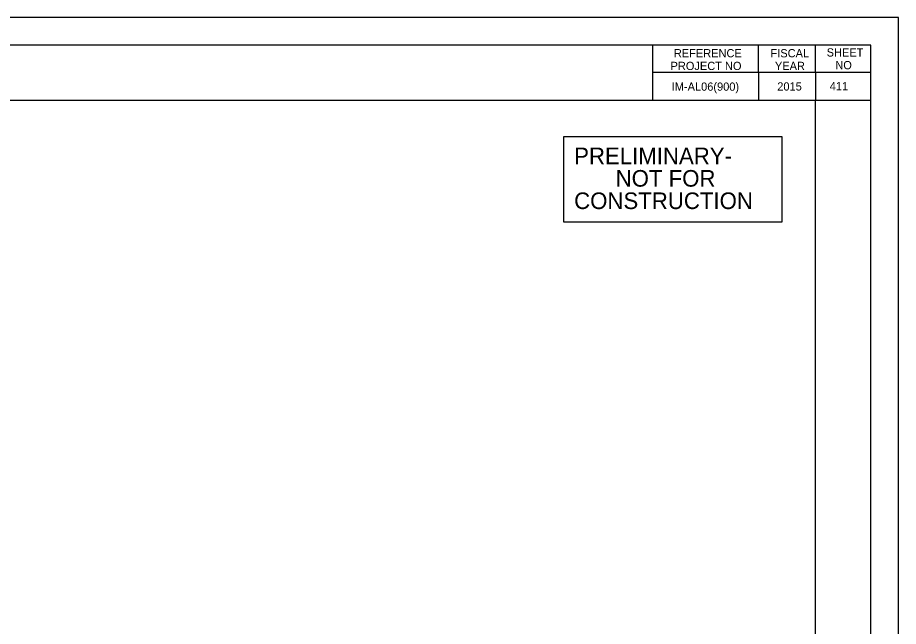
# Model space of a CAD drawing. Extents: x 1797478 to 1802796, y 246529 to 250952.
# Drawn here: x 1802636.8 to 1802796, y 250174.4 to 250284.4 of the extents above; entities that cross this region are included whole.
import ezdxf

# ---------------------------------------------------------------- set-up
doc = ezdxf.new("R2010")
doc.units = 0
for name, color, linetype in [('1', 7, 'Continuous'), ('2', 7, 'Continuous'), ('ANNO-SHT', 7, 'Continuous'), ('Level 6', 7, 'Continuous'), ('Level 62', 7, 'Continuous'), ('SHT-BDR', 7, 'Continuous'), ('SHT-BNDRY', 7, 'Continuous')]:
    doc.layers.add(name, color=color, linetype=linetype)

msp = doc.modelspace()

# ---------------------------------------------------------------- linework, layer by layer
at = {"layer": '1'}
msp.add_lwpolyline([(1802735.52, 250262.92), (1802774.93, 250262.92), (1802774.93, 250247.48), (1802735.52, 250247.48)], close=True, dxfattribs=at)
at = {"layer": '2'}
msp.add_lwpolyline([(1802780.97, 250227.57), (1802780.98, 250226.57)], dxfattribs=at)
msp.add_lwpolyline([(1802780.97, 250227.57), (1802780.98, 250226.57)], dxfattribs=at)
at = {"layer": 'Level 6'}
for p, q in [((1802751.55, 250279.42), (1802751.55, 250269.43)), ((1802770.71, 250274.42), (1802770.71, 250279.42)), ((1802781, 250274.55), (1802781, 250279.42)), ((1802791, 250274.48), (1802751.55, 250274.48)), ((1802770.71, 250274.42), (1802770.71, 250269.43)), ((1802781, 250274.55), (1802781, 250269.43)), ((1802791, 250269.43), (1802752.76, 250269.43))]:
    msp.add_line(p, q, dxfattribs=at)
at = {"layer": 'Level 62'}
msp.add_lwpolyline([(1802456, 250064.42), (1802796, 250064.42), (1802796, 250284.42), (1802456, 250284.42)], close=True, dxfattribs=at)
at = {"layer": 'SHT-BDR'}
msp.add_lwpolyline([(1802481, 250079.43), (1802781, 250079.43), (1802781, 250269.43), (1802481, 250269.43)], close=True, dxfattribs=at)
at = {"layer": 'SHT-BNDRY'}
msp.add_lwpolyline([(1802468.5, 250069.42), (1802791, 250069.42), (1802791, 250279.42), (1802468.5, 250279.42)], close=True, dxfattribs=at)

# ---------------------------------------------------------------- texts
at = {"layer": '1'}
for s, p in [('PRELIMINARY-', (1802737.39, 250257.94)), ('NOT FOR', (1802744.89, 250253.88)), ('CONSTRUCTION', (1802737.39, 250249.83))]:
    msp.add_text(s, height=3, dxfattribs=at).set_placement(p)
at = {"layer": 'ANNO-SHT'}
for s, height, p in [('IM-AL06(900)', 1.4899, (1802755.03, 250271.21)), ('2015', 1.49, (1802774.11, 250271.24)), ('  411  ', 1.49, (1802782.49, 250271.3))]:
    msp.add_text(s, height=height, rotation=360, dxfattribs=at).set_placement(p)
at = {"layer": 'Level 6'}
for s, p in [('REFERENCE', (1802755.42, 250277.25)), ('FISCAL', (1802772.89, 250277.25)), ('SHEET', (1802783.04, 250277.39)), ('PROJECT NO', (1802754.82, 250274.95)), ('YEAR', (1802773.69, 250274.95)), ('NO', (1802784.61, 250275.09))]:
    msp.add_text(s, height=1.488, dxfattribs=at).set_placement(p)

doc.saveas('drawing.dxf')
